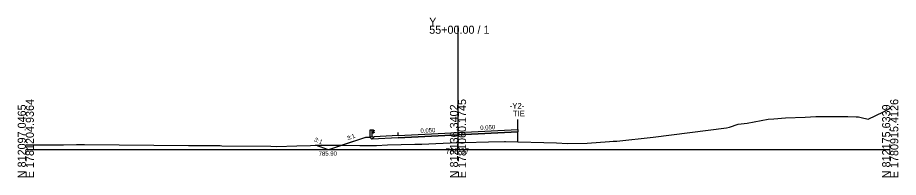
# Model space of a CAD drawing. Extents: x -12583 to 5303, y -44 to 25667.
# Drawn here: x 3997.2 to 4302.8, y 5490.3 to 5545.7 of the extents above; entities that cross this region are included whole.
import ezdxf

# ---------------------------------------------------------------- set-up
doc = ezdxf.new("R2010")
doc.units = 0
for name, color, linetype in [('Exist Cross Section Cell', 7, 'Continuous'), ('Exist XS Center Line Elevation Label', 7, 'Continuous'), ('Exist XS Ground Line', 7, 'Continuous'), ('Prop XS Ditch Standard Text', 7, 'Continuous'), ('Prop XS Dump Level', 7, 'Continuous'), ('Prop XS Earthwork Shape', 7, 'Continuous'), ('Prop XS Earthwork Undercut', 7, 'Continuous'), ('Prop XS EOT Tick Mark', 7, 'Continuous'), ('Prop XS Finish Grade', 7, 'Continuous'), ('Prop XS Finish Grade Earthwork', 7, 'Continuous'), ('Prop XS Finish Grade Paved Shoulder', 7, 'Continuous'), ('Prop XS Finish Grade Pavement', 7, 'Continuous'), ('Prop XS Guardrail', 7, 'Continuous'), ('Prop XS Label Text', 7, 'Continuous'), ('Prop XS Pvmt Edge Slope', 7, 'Continuous'), ('Prop XS SE Text', 7, 'Continuous'), ('Prop XS Side Slope Text', 7, 'Continuous'), ('Prop XS Subgrade Earthwork', 7, 'Continuous')]:
    doc.layers.add(name, color=color, linetype=linetype)

msp = doc.modelspace()

# ---------------------------------------------------------------- linework, layer by layer
at = {"layer": 'Exist Cross Section Cell'}
for p, q in [((4150, 5500), (4150, 5542.89)), ((4000, 5500), (4150, 5500)), ((4150, 5500), (4300, 5500))]:
    msp.add_line(p, q, dxfattribs=at)
at = {"layer": 'Exist XS Ground Line'}
for p, q in [((4292.41, 5510.5), (4297.64, 5513.02)), ((4297.64, 5513.02), (4300, 5514.3)), ((4244.28, 5507.67), (4247.28, 5508.8)), ((4247.28, 5508.8), (4250.4, 5509.1)), ((4250.4, 5509.1), (4257.69, 5510.54)), ((4257.69, 5510.54), (4259.56, 5510.65)), ((4259.56, 5510.65), (4263.62, 5510.9)), ((4263.62, 5510.9), (4270.47, 5511.2)), ((4270.47, 5511.2), (4274.21, 5511.36)), ((4274.21, 5511.36), (4277.32, 5511.38)), ((4277.32, 5511.38), (4285.35, 5511.36)), ((4285.35, 5511.36), (4288.21, 5511.27)), ((4288.21, 5511.27), (4288.99, 5511.33)), ((4288.99, 5511.33), (4289.93, 5511.02)), ((4289.93, 5511.02), (4292.41, 5510.5)), ((4217.76, 5504.3), (4243.2, 5507.43)), ((4243.2, 5507.43), (4244.28, 5507.67)), ((4137.39, 5501.78), (4149.68, 5502.37)), ((4149.68, 5502.37), (4150, 5502.37)), ((4150, 5502.37), (4152.19, 5502.4)), ((4152.19, 5502.4), (4160.6, 5502.6)), ((4160.6, 5502.6), (4166.12, 5502.7)), ((4166.12, 5502.7), (4166.44, 5502.7)), ((4166.44, 5502.7), (4184.21, 5502.25)), ((4194.78, 5502.18), (4202.53, 5502.69)), ((4202.53, 5502.69), (4203.84, 5502.81)), ((4203.84, 5502.81), (4204.25, 5502.82)), ((4204.25, 5502.82), (4205.09, 5502.88)), ((4205.09, 5502.88), (4217.76, 5504.3)), ((4000, 5501.55), (4004.8, 5501.54)), ((4004.8, 5501.54), (4008.56, 5501.57)), ((4008.56, 5501.57), (4013.04, 5501.64)), ((4013.04, 5501.64), (4017.63, 5501.74)), ((4017.63, 5501.74), (4020.32, 5501.73)), ((4020.32, 5501.73), (4056.44, 5501.33)), ((4056.44, 5501.33), (4058.34, 5501.31)), ((4058.34, 5501.31), (4059.93, 5501.31)), ((4059.93, 5501.31), (4067.5, 5501.31)), ((4067.5, 5501.31), (4068.02, 5501.29)), ((4068.02, 5501.29), (4085.07, 5501.07)), ((4085.07, 5501.07), (4087.05, 5500.99)), ((4087.05, 5500.99), (4094.06, 5501.24)), ((4094.06, 5501.24), (4103.57, 5501.51)), ((4103.57, 5501.51), (4115.88, 5501.4)), ((4115.88, 5501.4), (4121.69, 5501.37)), ((4121.69, 5501.37), (4125.51, 5501.53)), ((4125.51, 5501.53), (4130.29, 5501.7)), ((4130.29, 5501.7), (4135.01, 5501.78)), ((4135.01, 5501.78), (4137.39, 5501.78)), ((4184.21, 5502.25), (4188.05, 5502.09)), ((4188.05, 5502.09), (4194.78, 5502.18))]:
    msp.add_line(p, q, dxfattribs=at)
at = {"layer": 'Prop XS Dump Level'}
for p, q in [((4129.25, 5504.83), (4150, 5505.87)), ((4150, 5505.87), (4170.75, 5506.9))]:
    msp.add_line(p, q, dxfattribs=at)
at = {"layer": 'Prop XS Earthwork Shape'}
for points in [[(4117.89, 5504.17), (4109.74, 5501.45), (4115.88, 5501.4), (4121.69, 5501.37), (4125.51, 5501.53), (4130.29, 5501.7), (4135.01, 5501.78), (4137.39, 5501.78), (4149.68, 5502.37), (4150, 5502.37), (4152.19, 5502.4), (4160.6, 5502.6), (4166.12, 5502.7), (4166.44, 5502.7), (4170.75, 5502.59), (4170.75, 5506.11), (4150.04, 5505.08), (4129.29, 5504.04), (4120.06, 5503.58), (4119.35, 5504.29)], [(4103.57, 5501.51), (4109.74, 5501.45), (4105.08, 5499.9), (4100.5, 5501.42)]]:
    msp.add_lwpolyline(points, close=True, dxfattribs=at)
at = {"layer": 'Prop XS Earthwork Undercut'}
msp.add_line((4170.75, 5506.9), (4170.75, 5510.34), dxfattribs=at)
at = {"layer": 'Prop XS EOT Tick Mark'}
for p, q in [((4129.25, 5504.83), (4129.25, 5505.83)), ((4170.75, 5506.9), (4170.75, 5507.9))]:
    msp.add_line(p, q, dxfattribs=at)
at = {"layer": 'Prop XS Finish Grade'}
msp.add_line((4120.89, 5504.41), (4119.35, 5504.29), dxfattribs=at)
at = {"layer": 'Prop XS Finish Grade Earthwork'}
for p, q in [((4117.89, 5504.17), (4105.08, 5499.9)), ((4117.89, 5504.17), (4119.35, 5504.29)), ((4105.08, 5499.9), (4100.5, 5501.42))]:
    msp.add_line(p, q, dxfattribs=at)
at = {"layer": 'Prop XS Finish Grade Paved Shoulder'}
msp.add_line((4129.25, 5504.83), (4120.89, 5504.41), dxfattribs=at)
at = {"layer": 'Prop XS Finish Grade Pavement'}
for p, q in [((4129.25, 5504.83), (4150, 5505.87)), ((4150, 5505.87), (4170.75, 5506.9)), ((4170.75, 5506.9), (4170.75, 5506.11))]:
    msp.add_line(p, q, dxfattribs=at)
at = {"layer": 'Prop XS Guardrail'}
for p, q in [((4119.57, 5506.81), (4120.07, 5506.81)), ((4119.57, 5504.31), (4119.57, 5506.81)), ((4120.07, 5506.81), (4120.57, 5506.81)), ((4120.07, 5506.81), (4120.07, 5504.31)), ((4120.57, 5505.67), (4120.07, 5505.67)), ((4120.57, 5506.81), (4120.86, 5506.61)), ((4120.86, 5506.49), (4120.57, 5506.29)), ((4120.57, 5506.29), (4120.57, 5506.19)), ((4120.57, 5506.19), (4120.86, 5505.99)), ((4120.86, 5505.87), (4120.57, 5505.67)), ((4120.86, 5506.61), (4120.89, 5506.55)), ((4120.89, 5506.55), (4120.86, 5506.49)), ((4120.86, 5505.99), (4120.89, 5505.93)), ((4120.89, 5505.93), (4120.86, 5505.87))]:
    msp.add_line(p, q, dxfattribs=at)
at = {"layer": 'Prop XS Pvmt Edge Slope'}
msp.add_line((4120.89, 5504.41), (4120.06, 5503.58), dxfattribs=at)
at = {"layer": 'Prop XS Subgrade Earthwork'}
for p, q in [((4150.04, 5505.08), (4170.75, 5506.11)), ((4170.75, 5502.59), (4170.75, 5506.11)), ((4120.06, 5503.58), (4119.35, 5504.29)), ((4129.29, 5504.04), (4120.06, 5503.58)), ((4129.29, 5504.04), (4150.04, 5505.08))]:
    msp.add_line(p, q, dxfattribs=at)

# ---------------------------------------------------------------- texts
at = {"layer": 'Exist Cross Section Cell'}
for s, p in [('Y', (4140, 5542.89)), ('55+00.00 / 1', (4140, 5540.09))]:
    msp.add_text(s, height=2.8, dxfattribs=at).set_placement(p)
for s, p in [('N 812097.0465', (4000, 5490)), ('E 1781204.9364', (4002.8, 5490)), ('N 812136.3402', (4150, 5490)), ('E 1781060.1745', (4152.8, 5490)), ('N 812175.6339', (4300, 5490)), ('E 1780915.4126', (4302.8, 5490))]:
    msp.add_text(s, height=2.8, rotation=90, dxfattribs=at).set_placement(p)
at = {"layer": 'Exist XS Center Line Elevation Label'}
msp.add_text('788.37', height=2, dxfattribs=at).set_placement((4145.7, 5498.37))
at = {"layer": 'Prop XS Ditch Standard Text'}
msp.add_text('785.90', height=1.5, dxfattribs=at).set_placement((4101.65, 5497.83))
at = {"layer": 'Prop XS Label Text'}
for s, p in [('-Y2-', (4167.94, 5514.1)), ('TIE', (4169.04, 5511.47))]:
    msp.add_text(s, height=2, dxfattribs=at).set_placement(p)
at = {"layer": 'Prop XS SE Text'}
for p in [(4157.75, 5506.76), (4137, 5505.72)]:
    msp.add_text('0.050', height=1.5, rotation=2.8624, dxfattribs=at).set_placement(p)
at = {"layer": 'Prop XS Side Slope Text'}
for rotation, p in [(22.1863, (4111.82, 5503.07)), (338.2006, (4099.96, 5502.82))]:
    msp.add_text('3:1', height=1.5, rotation=rotation, dxfattribs=at).set_placement(p)

doc.saveas('drawing.dxf')
